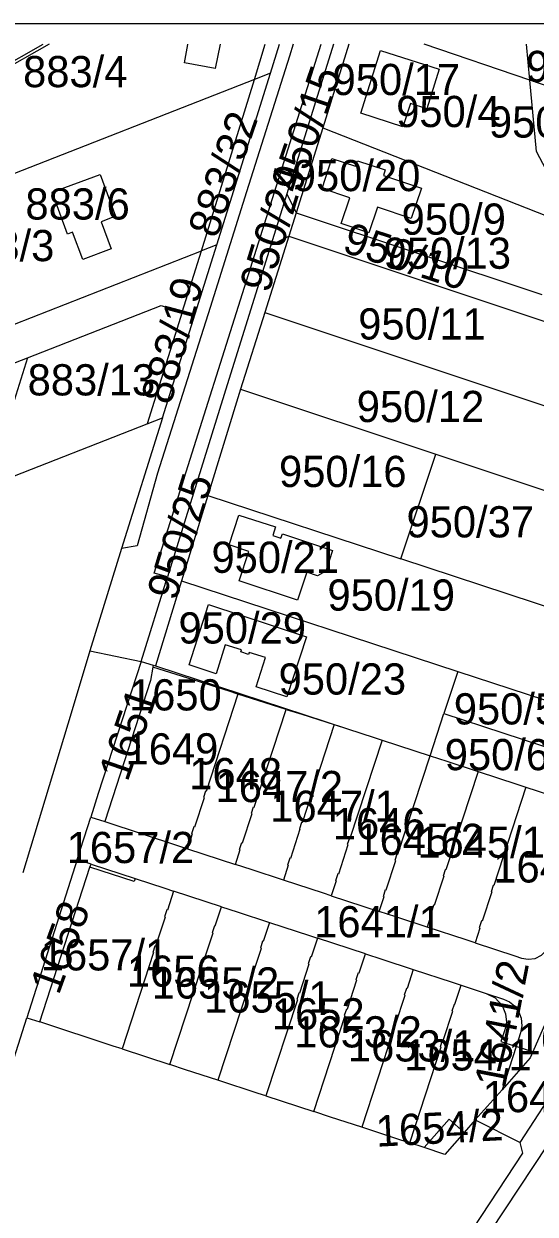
# Model space of a CAD drawing. Extents: x -583889 to -582839, y -1166553 to -1165068.
# Drawn here: x -583111.8 to -582997, y -1165334.9 to -1165067.8 of the extents above; entities that cross this region are included whole.
import ezdxf

# ---------------------------------------------------------------- set-up
doc = ezdxf.new("R2010")
doc.units = 0
for name, color, linetype in [('_parcely přehledka', 7, 'Continuous'), ('Hranice parcel', 7, 'Continuous'), ('Parcelní čísla', 7, 'Continuous')]:
    doc.layers.add(name, color=color, linetype=linetype)

msp = doc.modelspace()

# ---------------------------------------------------------------- linework, layer by layer
at = {"layer": '_parcely přehledka'}
msp.add_lwpolyline([(-583888.67, -1166552.78), (-582838.67, -1166552.78), (-582838.67, -1165067.78), (-583888.67, -1165067.78), (-583888.67, -1166552.78)], dxfattribs=at)
at = {"layer": 'Hranice parcel'}
for p, q in [((-583182.09, -1165114.62), (-583107.53, -1165072.33)), ((-583106.15, -1165072.33), (-583138.25, -1165090.53)), ((-583060.04, -1165080.27), (-583057.61, -1165072.33)), ((-583056.45, -1165078.88), (-583054.39, -1165072.33)), ((-583042.28, -1165072.33), (-583052.78, -1165105.96)), ((-583038.87, -1165072.33), (-583044.73, -1165091.1)), ((-582998.19, -1165080.46), (-583021.98, -1165072.33)), ((-582998.19, -1165080.46), (-582998.97, -1165072.33)), ((-583060.04, -1165080.27), (-583145.52, -1165113.73)), ((-583071.94, -1165118.73), (-583060.04, -1165080.27)), ((-583068.53, -1165117.4), (-583056.45, -1165078.88)), ((-583056.45, -1165078.88), (-583060.04, -1165080.27)), ((-582989.08, -1165083.58), (-582998.19, -1165080.46)), ((-583044.73, -1165091.1), (-583050.67, -1165110.17)), ((-583044.73, -1165091.1), (-582992.03, -1165111.81)), ((-583052.78, -1165105.96), (-583056.37, -1165117.45)), ((-583052.78, -1165105.96), (-583050.67, -1165110.17)), ((-583050.67, -1165110.17), (-583052.33, -1165115.41)), ((-583050.67, -1165110.17), (-582995.55, -1165128.53)), ((-583052.33, -1165115.41), (-583057.74, -1165132.59)), ((-583056.37, -1165117.45), (-583052.33, -1165115.41)), ((-583052.33, -1165115.41), (-582994.16, -1165134.79)), ((-583080.7, -1165156.18), (-583068.53, -1165117.4)), ((-583068.53, -1165117.4), (-583071.94, -1165118.73)), ((-583157.61, -1165152.25), (-583071.94, -1165118.73)), ((-583076.26, -1165132.5), (-583071.94, -1165118.73)), ((-583076.26, -1165132.5), (-583084.11, -1165157.51)), ((-583057.74, -1165132.59), (-583063.16, -1165149.76)), ((-583057.74, -1165132.59), (-582990.33, -1165155.04)), ((-583137.89, -1165153.24), (-583111.02, -1165142.73)), ((-583111.02, -1165142.73), (-583120.08, -1165171.59)), ((-583063.16, -1165149.76), (-583070.52, -1165173.65)), ((-583063.16, -1165149.76), (-583019.35, -1165164.35)), ((-583120.08, -1165171.59), (-583084.11, -1165157.51)), ((-583080.7, -1165156.18), (-583089.9, -1165185.49)), ((-583084.11, -1165157.51), (-583080.7, -1165156.18)), ((-583027.19, -1165187.87), (-583019.35, -1165164.35)), ((-583019.35, -1165164.35), (-582985.47, -1165175.64)), ((-583070.52, -1165173.65), (-583076.41, -1165192.76)), ((-583070.52, -1165173.65), (-583027.19, -1165187.87)), ((-583089.9, -1165185.49), (-583097.01, -1165208.5)), ((-582983.21, -1165202.31), (-583027.19, -1165187.87)), ((-583085.46, -1165210.84), (-583079.6, -1165191.86)), ((-583076.41, -1165192.76), (-583082.3, -1165211.87)), ((-583076.41, -1165192.76), (-583014.39, -1165213.12)), ((-583097.01, -1165208.5), (-583085.46, -1165210.84)), ((-583085.46, -1165210.84), (-583082.79, -1165211.71)), ((-583082.79, -1165211.71), (-583082.89, -1165212.12)), ((-583082.79, -1165211.71), (-583082.3, -1165211.87)), ((-583082.3, -1165211.87), (-583039.19, -1165225.97)), ((-583014.39, -1165213.12), (-583017.5, -1165222.52)), ((-583014.39, -1165213.12), (-582983.03, -1165223.42)), ((-583052.95, -1165221.61), (-583063.75, -1165218.19)), ((-583020.63, -1165232.04), (-583017.5, -1165222.52)), ((-583017.5, -1165222.52), (-582983.91, -1165233.54)), ((-583042.16, -1165225.03), (-583039.19, -1165225.97)), ((-583031.38, -1165228.52), (-583020.63, -1165232.04)), ((-582999.09, -1165239.08), (-582984.95, -1165243.7)), ((-583099.84, -1165255.32), (-583096.8, -1165245.8)), ((-583096.8, -1165245.8), (-583093.68, -1165246.81)), ((-583075.1, -1165252.89), (-583064.33, -1165256.41)), ((-583099.84, -1165255.32), (-583111.16, -1165290.82)), ((-583108.21, -1165291.77), (-583096.98, -1165257.04)), ((-583096.75, -1165256.33), (-583099.84, -1165255.32)), ((-583096.98, -1165257.04), (-583096.75, -1165256.33)), ((-583096.75, -1165256.33), (-583086.86, -1165259.56)), ((-583067.44, -1165265.91), (-583078.2, -1165262.4)), ((-583042.8, -1165263.45), (-583032.04, -1165266.97)), ((-583035.15, -1165276.47), (-583045.91, -1165272.96)), ((-583013.61, -1165283.51), (-583008.01, -1165285.35)), ((-583000.42, -1165318.79), (-582978.28, -1165284.82)), ((-583111.16, -1165290.82), (-583108.21, -1165291.77)), ((-583001.29, -1165297.28), (-583004.46, -1165306.99)), ((-582997.54, -1165298.5), (-583001.29, -1165297.28)), ((-583089.78, -1165297.8), (-583079.02, -1165301.32)), ((-583004.46, -1165306.99), (-583010.46, -1165313.76)), ((-583057.48, -1165308.36), (-583046.72, -1165311.88)), ((-582987.21, -1165308.59), (-583007.11, -1165338.81)), ((-583010.46, -1165313.76), (-583012.95, -1165316.56)), ((-583010.46, -1165313.76), (-583000.42, -1165318.79)), ((-583021.97, -1165319.97), (-583025.19, -1165318.92))]:
    msp.add_line(p, q, dxfattribs=at)
for points in [[(-583051.35, -1165072.33), (-583052.21, -1165075.04), (-583061.84, -1165105.52), (-583070.03, -1165131.41), (-583081.8, -1165168.62), (-583086.42, -1165184.92), (-583089.9, -1165185.49)], [(-583079.6, -1165191.86), (-583082.58, -1165191.02), (-583055.97, -1165106.96), (-583045.04, -1165072.33)], [(-583067.77, -1165072.33), (-583068.86, -1165077.84), (-583075.75, -1165076.5), (-583074.98, -1165072.41)], [(-583074.98, -1165072.41), (-583075.04, -1165072.33)], [(-583018.54, -1165077.97), (-583021.36, -1165086.84), (-583025.04, -1165085.68), (-583026.7, -1165090.87), (-583036.17, -1165087.85), (-583031.72, -1165073.8), (-583018.54, -1165077.97)], [(-582993.15, -1165103.26), (-582996.72, -1165096.42), (-582998.19, -1165080.46)], [(-583040.56, -1165112.58), (-583038.67, -1165106.86), (-583044.88, -1165104.75), (-583042.67, -1165098.02), (-583037.36, -1165099.76), (-583036.94, -1165098.49), (-583030.68, -1165100.55), (-583031.11, -1165101.82), (-583022.56, -1165104.69), (-583024.83, -1165111.46), (-583032.42, -1165108.92), (-583034.34, -1165114.66), (-583040.56, -1165112.58)], [(-583098.6, -1165120.64), (-583100.87, -1165114.55), (-583102, -1165114.97), (-583105.48, -1165105.59), (-583094.71, -1165101.6), (-583091.22, -1165110.97), (-583094.5, -1165112.18), (-583092.23, -1165118.28), (-583098.6, -1165120.64)], [(-583056.37, -1165117.45), (-583066.15, -1165148.76), (-583079.6, -1165191.86)], [(-583111.02, -1165142.73), (-583081.03, -1165131), (-583076.26, -1165132.5)], [(-583045.92, -1165191.63), (-583048.29, -1165190.84), (-583050.36, -1165197.14), (-583063.52, -1165192.81), (-583061.35, -1165186.19), (-583065.73, -1165184.7), (-583063.54, -1165178.01), (-583055.34, -1165180.64), (-583055.96, -1165182.62), (-583054.1, -1165183.17), (-583053.75, -1165182.24), (-583042.54, -1165185.94), (-583044, -1165190.61), (-583045.92, -1165191.63)], [(-583066.59, -1165207.14), (-583068.66, -1165213.66), (-583074.74, -1165211.65), (-583070.37, -1165198.11), (-583048.33, -1165205.32), (-583052.75, -1165218.84), (-583059.66, -1165216.57), (-583057.58, -1165210), (-583061.22, -1165208.84), (-583061.36, -1165209.27), (-583063.09, -1165208.73), (-583062.95, -1165208.29), (-583066.59, -1165207.14)], [(-583097.01, -1165208.5), (-583101.24, -1165222.44), (-583112.09, -1165258.27)], [(-583085.46, -1165210.84), (-583095.12, -1165240.52), (-583096.8, -1165245.8)], [(-583082.89, -1165212.12), (-583083.36, -1165215.12), (-583093.68, -1165246.81)], [(-583063.75, -1165218.19), (-583065.72, -1165217.56), (-583082.89, -1165212.12)], [(-583063.75, -1165218.19), (-583070.89, -1165240.03), (-583071.03, -1165239.99), (-583071.5, -1165241.41), (-583071.36, -1165241.46), (-583073.5, -1165248.02), (-583073.64, -1165247.97), (-583074.15, -1165249.52), (-583074.01, -1165249.56), (-583075.1, -1165252.89)], [(-583064.33, -1165256.41), (-583063.24, -1165253.08), (-583063.39, -1165253.04), (-583062.88, -1165251.49), (-583062.74, -1165251.54), (-583060.59, -1165244.98), (-583060.74, -1165244.93), (-583060.27, -1165243.51), (-583060.13, -1165243.55), (-583052.95, -1165221.61)], [(-583052.95, -1165221.61), (-583049.42, -1165222.73), (-583042.16, -1165225.03)], [(-583042.16, -1165225.03), (-583049.36, -1165247.07), (-583049.51, -1165247.03), (-583049.97, -1165248.45), (-583049.83, -1165248.5), (-583051.97, -1165255.06), (-583052.12, -1165255.01), (-583052.62, -1165256.56), (-583052.48, -1165256.6), (-583053.56, -1165259.93)], [(-583039.19, -1165225.97), (-583033.14, -1165227.95), (-583031.38, -1165228.52)], [(-583031.38, -1165228.52), (-583038.6, -1165250.59), (-583038.74, -1165250.55), (-583039.21, -1165251.97), (-583039.06, -1165252.02), (-583041.21, -1165258.58), (-583041.35, -1165258.53), (-583041.86, -1165260.08), (-583041.71, -1165260.12), (-583042.8, -1165263.45)], [(-583032.04, -1165266.97), (-583030.95, -1165263.64), (-583031.09, -1165263.6), (-583030.59, -1165262.05), (-583030.44, -1165262.1), (-583028.3, -1165255.54), (-583028.44, -1165255.49), (-583027.98, -1165254.07), (-583027.83, -1165254.11), (-583020.63, -1165232.04)], [(-583020.63, -1165232.04), (-583016.89, -1165233.26), (-583009.85, -1165235.56)], [(-583009.85, -1165235.56), (-583017.07, -1165257.63), (-583017.21, -1165257.59), (-583017.68, -1165259.01), (-583017.54, -1165259.06), (-583019.68, -1165265.62), (-583019.82, -1165265.57), (-583020.33, -1165267.11), (-583020.19, -1165267.16), (-583021.27, -1165270.49)], [(-583009.85, -1165235.56), (-583001.11, -1165238.42), (-582999.09, -1165239.08)], [(-582999.09, -1165239.08), (-583006.31, -1165261.15), (-583006.45, -1165261.11), (-583006.92, -1165262.53), (-583006.77, -1165262.58), (-583008.92, -1165269.14), (-583009.06, -1165269.09), (-583009.56, -1165270.63), (-583009.42, -1165270.68), (-583010.51, -1165274.01)], [(-583093.68, -1165246.81), (-583077.07, -1165252.25), (-583075.1, -1165252.89)], [(-583086.86, -1165259.56), (-583087.09, -1165260.28), (-583096.98, -1165257.04)], [(-583053.56, -1165259.93), (-583060.81, -1165257.56), (-583064.33, -1165256.41)], [(-583086.86, -1165259.56), (-583080.18, -1165261.75), (-583078.2, -1165262.4)], [(-583042.8, -1165263.45), (-583044.56, -1165262.87), (-583053.56, -1165259.93)], [(-583078.2, -1165262.4), (-583079.6, -1165266.67), (-583079.74, -1165266.63), (-583080.25, -1165268.17), (-583080.11, -1165268.22), (-583082.25, -1165274.77), (-583082.39, -1165274.73), (-583082.86, -1165276.15), (-583082.72, -1165276.2), (-583089.78, -1165297.8)], [(-583079.02, -1165301.32), (-583071.95, -1165279.72), (-583072.09, -1165279.67), (-583071.63, -1165278.25), (-583071.49, -1165278.29), (-583069.34, -1165271.74), (-583069.48, -1165271.69), (-583068.98, -1165270.15), (-583068.84, -1165270.19), (-583067.44, -1165265.91)], [(-583067.44, -1165265.91), (-583063.92, -1165267.06), (-583056.67, -1165269.43)], [(-583021.27, -1165270.49), (-583028.31, -1165268.19), (-583032.04, -1165266.97)], [(-583010.51, -1165274.01), (-583001.61, -1165276.92), (-583000.06, -1165277.42), (-582998.56, -1165277.7), (-582997.02, -1165277.49), (-582995.62, -1165276.78), (-582994.54, -1165275.76), (-582993.75, -1165274.23), (-582991.64, -1165267.79), (-582988.32, -1165268.87)], [(-583056.67, -1165269.43), (-583058.07, -1165273.71), (-583058.21, -1165273.66), (-583058.72, -1165275.21), (-583058.58, -1165275.26), (-583060.72, -1165281.81), (-583060.86, -1165281.77), (-583061.33, -1165283.19), (-583061.19, -1165283.24), (-583068.25, -1165304.84)], [(-583056.67, -1165269.43), (-583047.67, -1165272.38), (-583045.91, -1165272.96)], [(-583010.51, -1165274.01), (-583012.53, -1165273.35), (-583021.27, -1165270.49)], [(-583045.91, -1165272.96), (-583047.31, -1165277.23), (-583047.45, -1165277.18), (-583047.96, -1165278.73), (-583047.81, -1165278.77), (-583049.96, -1165285.33), (-583050.1, -1165285.29), (-583050.57, -1165286.71), (-583050.42, -1165286.76), (-583057.48, -1165308.36)], [(-583046.72, -1165311.88), (-583039.66, -1165290.28), (-583039.8, -1165290.23), (-583039.34, -1165288.81), (-583039.19, -1165288.85), (-583037.05, -1165282.29), (-583037.19, -1165282.25), (-583036.69, -1165280.7), (-583036.54, -1165280.75), (-583035.15, -1165276.47)], [(-583035.15, -1165276.47), (-583031.42, -1165277.69), (-583024.38, -1165279.99)], [(-582990.16, -1165276.9), (-582992.4, -1165286.65), (-582997.54, -1165298.5)], [(-583024.38, -1165279.99), (-583025.78, -1165284.27), (-583025.92, -1165284.22), (-583026.43, -1165285.77), (-583026.29, -1165285.81), (-583028.43, -1165292.37), (-583028.57, -1165292.33), (-583029.04, -1165293.75), (-583028.9, -1165293.8), (-583035.96, -1165315.4)], [(-583024.38, -1165279.99), (-583015.64, -1165282.84), (-583013.61, -1165283.51)], [(-583025.19, -1165318.92), (-583018.13, -1165297.32), (-583018.27, -1165297.27), (-583017.81, -1165295.85), (-583017.67, -1165295.89), (-583015.52, -1165289.33), (-583015.66, -1165289.29), (-583015.16, -1165287.74), (-583015.02, -1165287.79), (-583013.61, -1165283.51)], [(-583008.01, -1165285.35), (-583004.1, -1165286.63), (-583002.78, -1165287.23), (-583001.69, -1165288.11), (-583000.76, -1165289.33), (-583000.13, -1165290.91), (-582999.98, -1165292.65), (-583000.28, -1165294.2), (-583001.29, -1165297.28)], [(-583008.01, -1165285.35), (-583006.02, -1165286.36), (-583004.46, -1165288.06), (-583003.68, -1165289.92), (-583003.47, -1165291.82), (-583003.85, -1165293.55), (-583004.7, -1165296.16), (-583001.29, -1165297.28)], [(-583184.72, -1165523.62), (-583182.81, -1165517.68), (-583176.05, -1165496.65), (-583169.59, -1165475.46), (-583156.46, -1165434.65), (-583140.6, -1165385.28), (-583126.45, -1165339.09), (-583115, -1165302.85), (-583111.16, -1165290.82)], [(-583089.78, -1165297.8), (-583091.75, -1165297.16), (-583108.21, -1165291.77)], [(-582997.54, -1165298.5), (-582998.11, -1165299.82), (-583004.46, -1165306.99)], [(-583068.25, -1165304.84), (-583075.5, -1165302.47), (-583079.02, -1165301.32)], [(-583057.48, -1165308.36), (-583059.24, -1165307.78), (-583068.25, -1165304.84)], [(-583035.96, -1165315.4), (-583042.99, -1165313.1), (-583046.72, -1165311.88)], [(-583025.19, -1165318.92), (-583027.21, -1165318.26), (-583035.96, -1165315.4)], [(-583021.97, -1165319.97), (-583016.31, -1165313.58), (-583012.95, -1165316.56)], [(-583150.03, -1165547.02), (-583146.45, -1165545.26), (-583081.48, -1165445.65), (-583060.78, -1165413.9), (-582999.79, -1165321.21), (-583000.42, -1165318.79)], [(-583012.95, -1165316.56), (-583017.31, -1165321.49), (-583021.97, -1165319.97)]]:
    msp.add_lwpolyline(points, dxfattribs=at)

# ---------------------------------------------------------------- texts
at = {"layer": 'Parcelní čísla'}
for s, p in [('883/4', (-583112, -1165082)), ('950/14', (-582999.09, -1165080.84)), ('950/17', (-583042.5, -1165083.77)), ('950/4', (-583028.23, -1165090.95)), ('950/5', (-583007.4, -1165093.31)), ('950/20', (-583051.43, -1165105.33)), ('883/6', (-583111.47, -1165111.7)), ('950/9', (-583027.01, -1165115.1)), ('883/3', (-583128.41, -1165121.04)), ('950/13', (-583031.07, -1165122.75)), ('950/11', (-583036.75, -1165138.62)), ('883/13', (-583110.98, -1165151.17)), ('950/12', (-583037.08, -1165157.15)), ('950/16', (-583054.53, -1165171.72)), ('950/37', (-583025.91, -1165183.03)), ('950/21', (-583069.7, -1165190.98)), ('950/19', (-583043.66, -1165199.46)), ('950/29', (-583077.11, -1165206.84)), ('950/23', (-583054.63, -1165218.3)), ('1650', (-583088.22, -1165221.86)), ('950/59', (-583015.29, -1165225)), ('1649', (-583088.99, -1165233.98)), ('950/60', (-583017.32, -1165235.27)), ('1648', (-583074.68, -1165239.53)), ('1647/2', (-583068.79, -1165242.43)), ('1647/1', (-583056.49, -1165246.85)), ('1646', (-583042.46, -1165250.76)), ('1657/2', (-583102.21, -1165256.11)), ('1645/2', (-583037.15, -1165254.29)), ('1645/1', (-583023.47, -1165254.92)), ('1643', (-583006.41, -1165260.47)), ('1641/1', (-583046.64, -1165272.76)), ('1657/1', (-583108.03, -1165280.2)), ('1656', (-583088.7, -1165283.86)), ('1655/2', (-583083.13, -1165286.51)), ('1655/1', (-583071.35, -1165289.66)), ('1652', (-583056.14, -1165293.44)), ('1653/2', (-583051.1, -1165297.48)), ('1639', (-583000.96, -1165299.02)), ('1653/1', (-583039.06, -1165300.63)), ('1654/1', (-583026.44, -1165302.65)), ('1640', (-583008.79, -1165312.01))]:
    msp.add_text(s, height=7, dxfattribs=at).set_placement(p)
for s, rotation, p in [('950/15', 71, (-583049.86, -1165105.93)), ('883/32', 71, (-583068.51, -1165116.15)), ('950/24', 73, (-583056.83, -1165128.44)), ('950/10', 342, (-583040.6, -1165118.87)), ('883/19', 75, (-583078.85, -1165153.51)), ('950/25', 73, (-583077.64, -1165197.48)), ('1651', 71, (-583088.55, -1165238.08)), ('1658', 70, (-583104, -1165285.91)), ('1641/2', 79, (-583003.83, -1165306.86)), ('1654/2', 3, (-583032.62, -1165319.77))]:
    msp.add_text(s, height=7, rotation=rotation, dxfattribs=at).set_placement(p)

doc.saveas('drawing.dxf')
